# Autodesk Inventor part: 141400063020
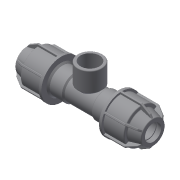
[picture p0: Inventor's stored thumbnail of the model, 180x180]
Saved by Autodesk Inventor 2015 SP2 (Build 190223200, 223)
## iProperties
Created: 2017-08
Part Number: 141400063020
Material: Generic
Description: PLASSON L.14 TEE FEMALE ADAPTOR (SILVER) 63 x 2" x 63
Document SubType Name: Modeling
Designer: KIM
Density: 1 g/cm^3
Appearance: Default
Author: KIM
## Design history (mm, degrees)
derived "141400.ipt"
feature "Solid1::141400.ipt"
feature "Solid2::141400.ipt"
tag "TaggingFeature1"
body "Solid1"
other parameters: "d1" = 63, "d2" = 82, "d4" = 15 deg, "d5" = 54.12, "d6" = 17.8596, "d10" = 106, "d16" = 64.26, "d17" = 4.1, "d22" = 100.8, "d24" = 4.1, "d25" = 95.4, "d26" = 79.5, "d27" = 4.1, "d28" = 135 deg, "d29" = 2.46, "d31" = 3.15, "d46" = 150 deg, "d49" = 5.3, "d50" = 0, "d58" = 1.89, "d61" = 360 deg, "d63" = 56.7, "d64" = 119.5, "d80" = 90.72, "d81" = 5.04, "d84" = 4.1, "d94" = 86, "d95" = 56.656, "d96" = 73.6528, "d98" = 50.4, "d99" = 66.28752, "d100" = 135 deg, "d108" = 3.15, "d111" = 0, "d_" = 63, "G_" = 56.656, "E_" = 106, "H_" = 239, "l_" = 82, "A_" = 86
